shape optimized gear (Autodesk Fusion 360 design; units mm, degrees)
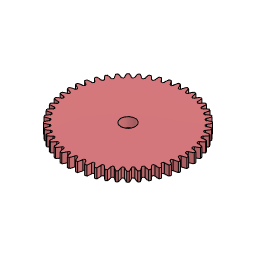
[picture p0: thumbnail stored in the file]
description: Spur Gear; Module: 2.0; Num Teeth: 48; Pressure Angle: 20.0; Backlash: 0.00 mm
sketch "Sketch1" plane through (0, 0, 0) normal (0, 0, 1) x axis (1, 0, 0)
  circle C1 centre (0, 0) radius 45.5492
  circle C2 centre (0, 0) radius 6
extrude "Extrude1" new body sketch "Sketch1" along normal blind 8
sketch "Sketch2" plane through (0, 0, 0) normal (0, 0, 1) x axis (1, 0, 0)
  curve K1 (49.994, -0.7729) -> (45.0541, -2.1475)
  curve K2 (49.994, 0.7729) -> (45.0541, 2.1475)
  line L1 (45.0541, -2.1475) -> (45.0541, 2.1475)
  arc A1 centre (0, 0) radius 50 clockwise from (49.994, 0.7729) to (49.994, -0.7729)
extrude "Extrude2" add sketch "Sketch2" along normal blind 8
fillet "Fillet1" radius 1.1
circular_pattern "C-Pattern1" countU 48 TotalAngle 360
sketch "Sketch3" plane through (0, 0, 0) normal (0, 0, 1) x axis (1, 0, 0)
  circle C1 centre (0, 0) radius 48
ground "Ground1"
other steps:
create_component "CreateComponent1"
